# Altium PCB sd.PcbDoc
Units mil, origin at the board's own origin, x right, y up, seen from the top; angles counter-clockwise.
Board outline 6000 x 4000 mil, 2 copper layers (Top Layer, Bottom Layer); 11 components, 11 nets, 49 pads, 4 vias.
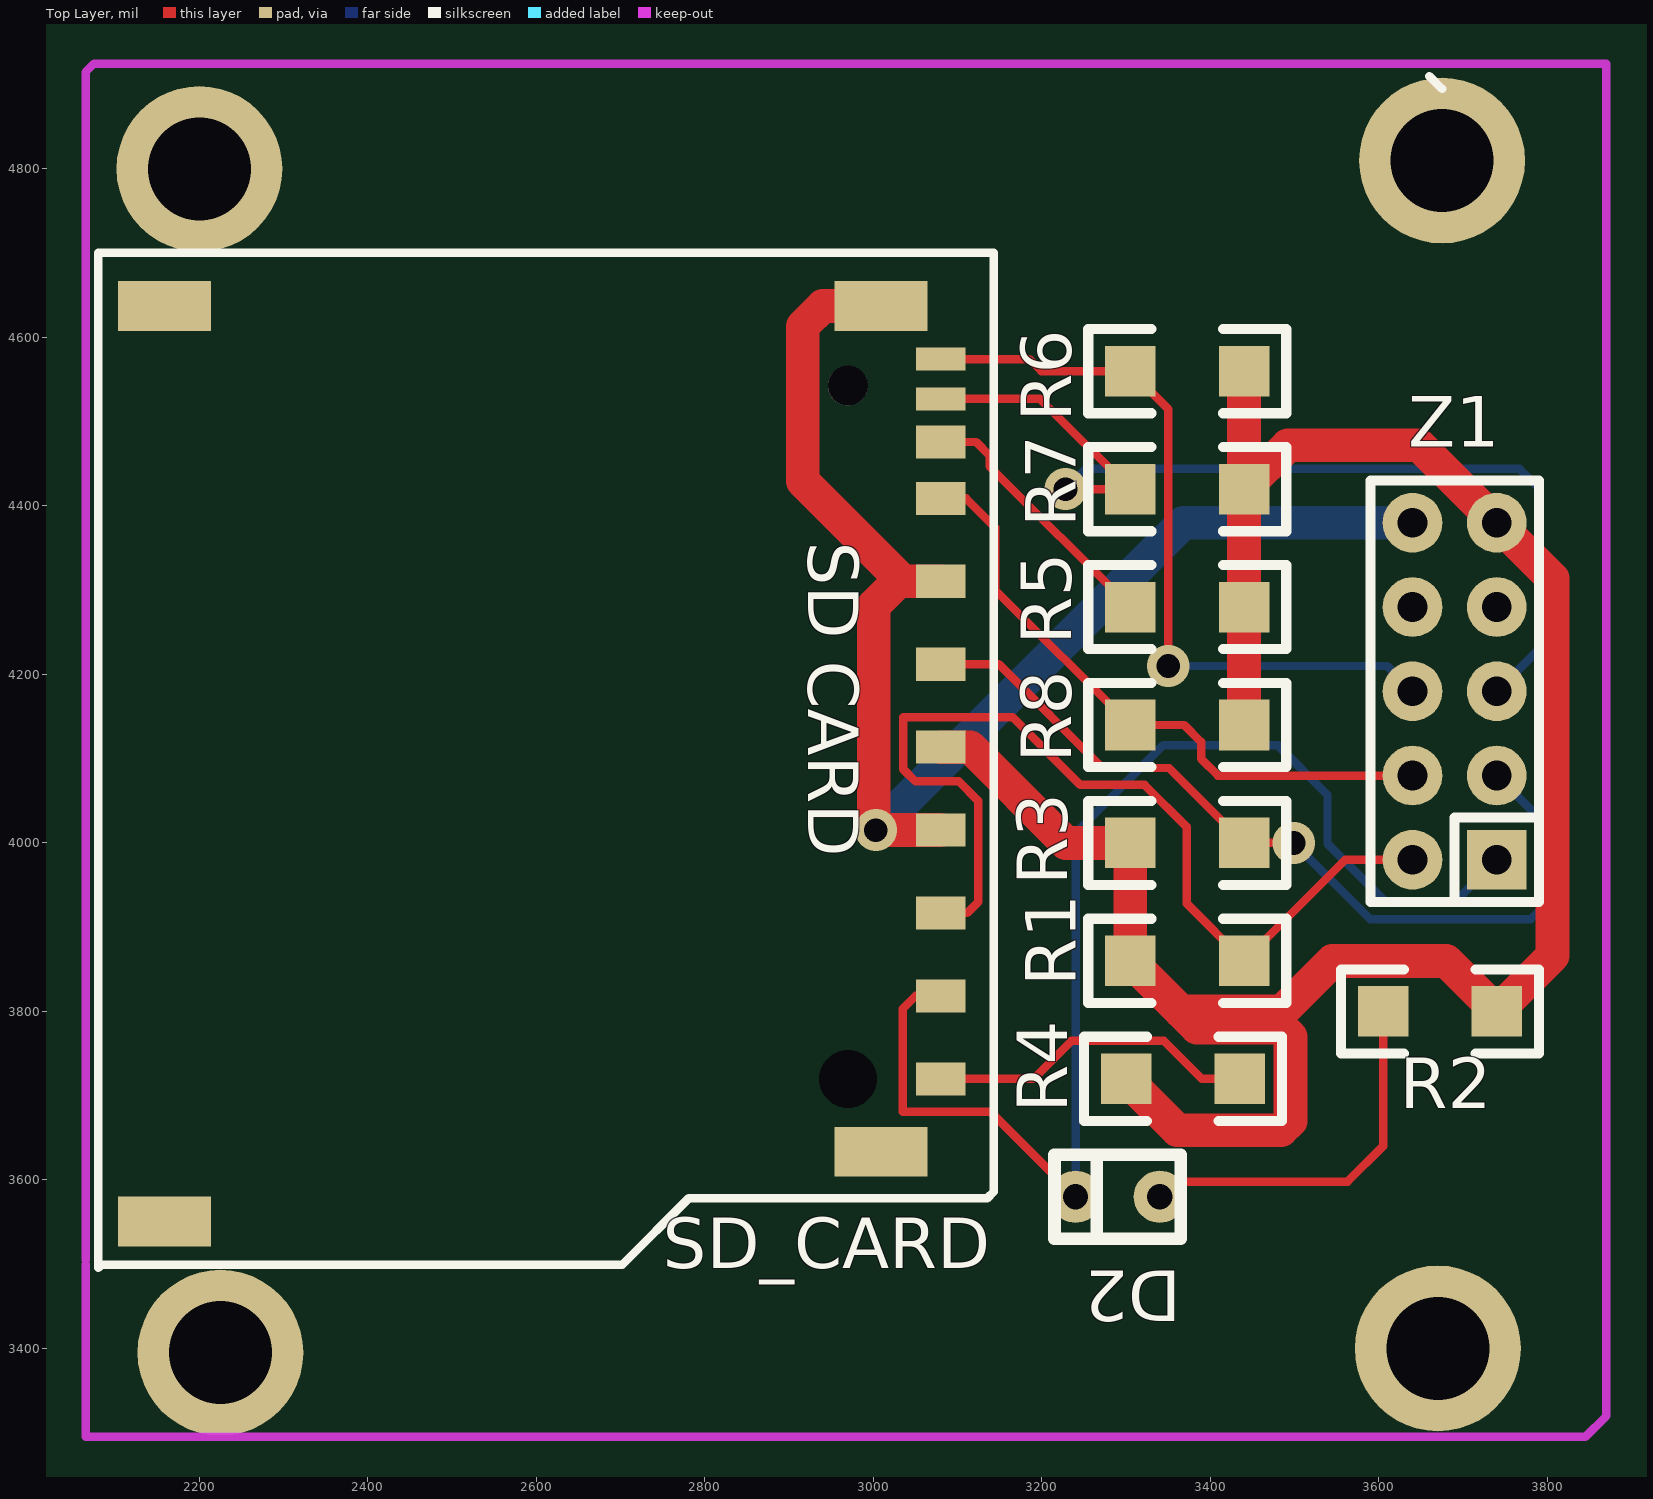
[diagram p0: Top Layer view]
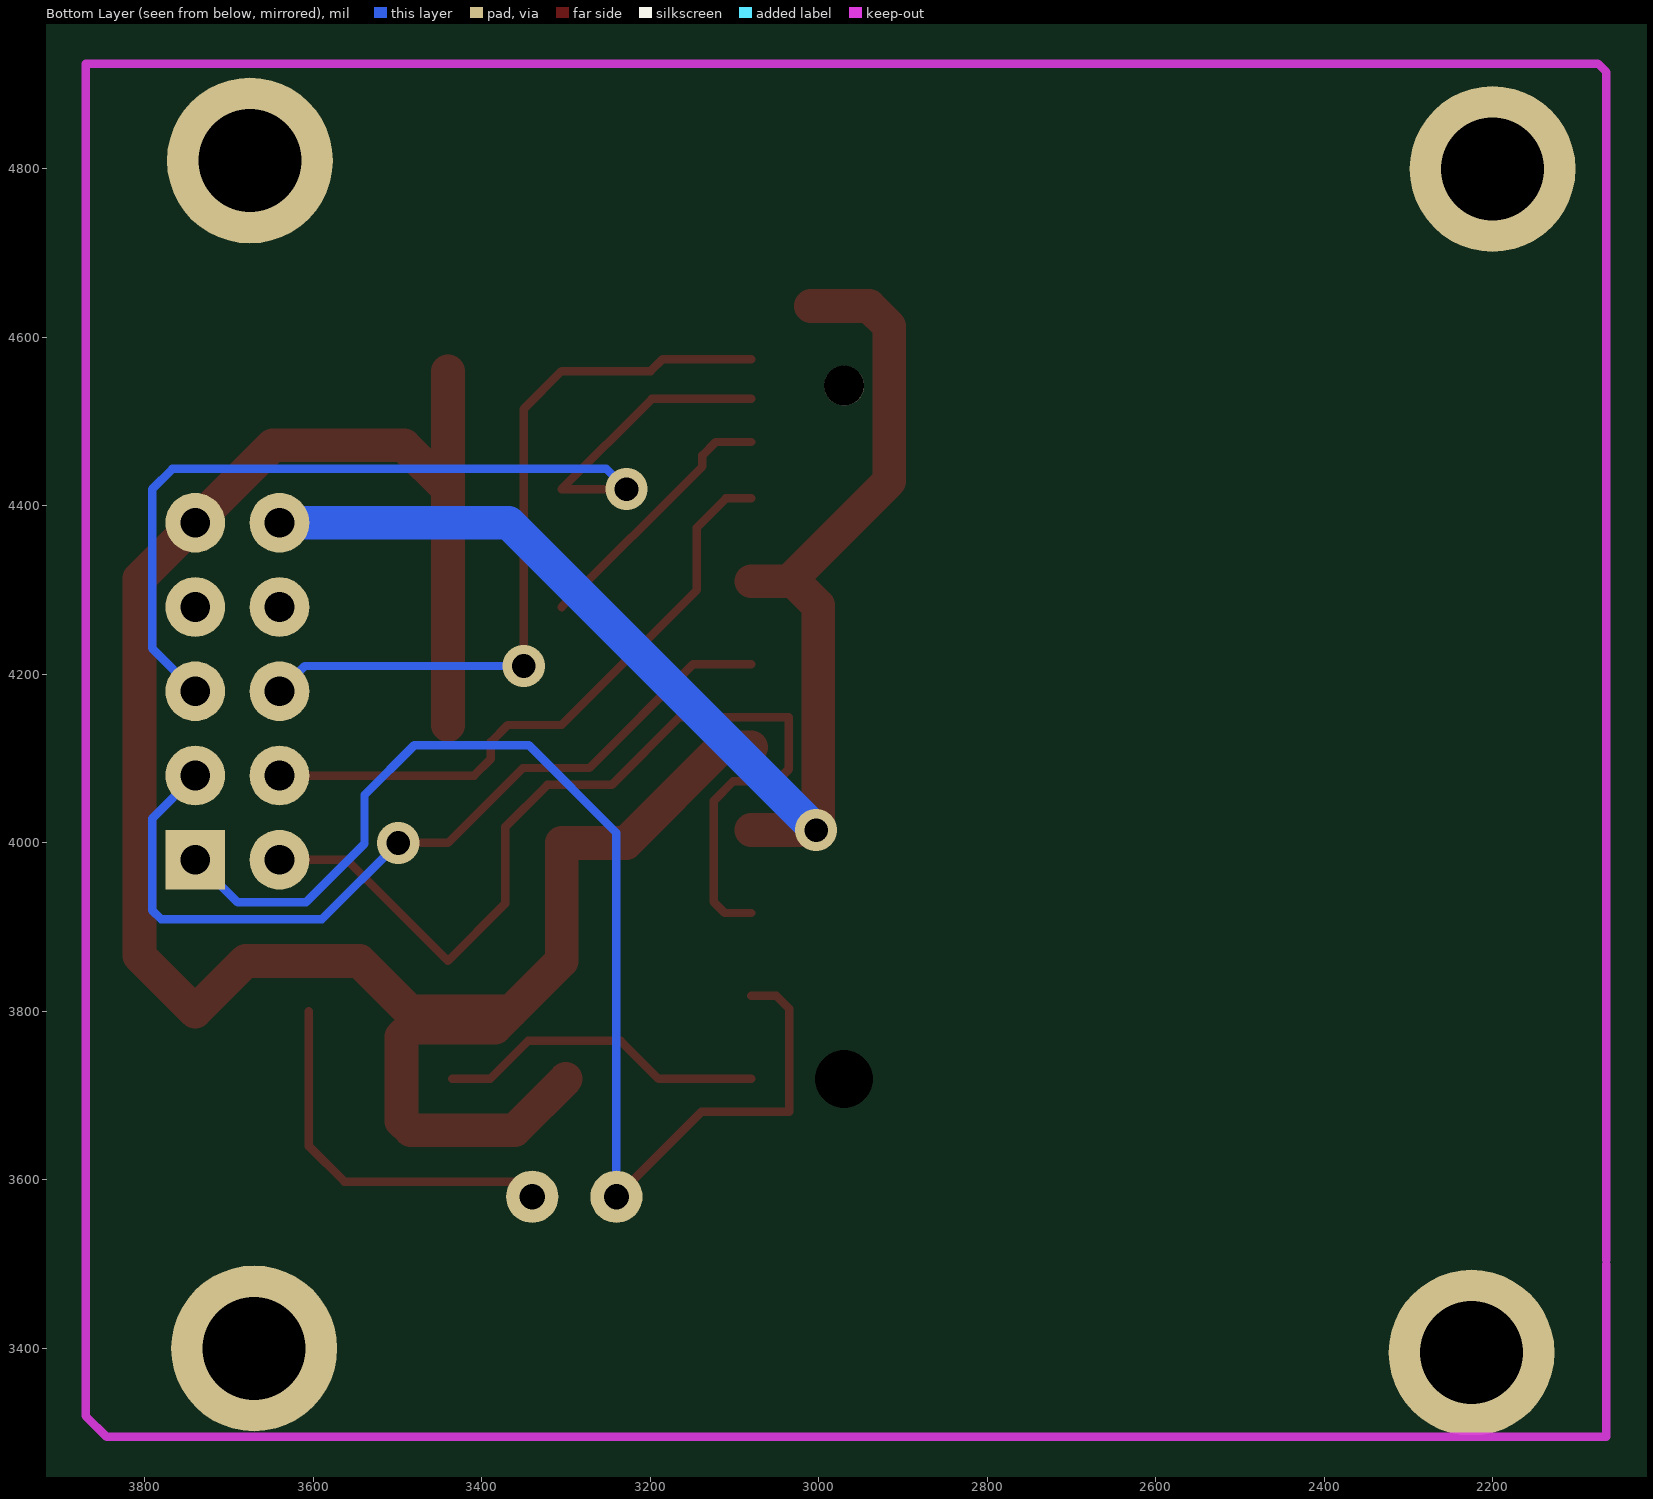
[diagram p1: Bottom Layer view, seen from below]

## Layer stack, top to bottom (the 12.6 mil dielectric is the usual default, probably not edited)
Top Layer: signal copper 1.4
Dielectric: dielectric 12.6, FR-4, Dk 4.8
Bottom Layer: signal copper 1.4

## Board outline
1000,1000 7000,1000 7000,5000 1000,5000

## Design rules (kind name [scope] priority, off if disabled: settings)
Clearance [All] p1: gap=10
PolygonConnect [All] p1: connectstyle=Relief reliefconductorwidth=10 reliefentries=4 polygonreliefangle="90 Angle"
RoutingVias [All] p1: holewidth=28 width=50 viastyle="Through Hole" minholewidth=28 minwidth=50 maxholewidth=28 maxwidth=50
SilkscreenOverComponentPads [All] p1: minsilkscreentomaskgap=10
SolderMaskExpansion [All] p1: expansion=4
Width Width_2 [InNet('GND')] p1: maxlimit=40 minlimit=40 preferedwidth=40
Width Width_1 [InNet('+3,3V')] p2: maxlimit=40 minlimit=40 preferedwidth=40
Width [All] p3: maxlimit=10 minlimit=10 preferedwidth=10
27 further rules are at their usual default settings.

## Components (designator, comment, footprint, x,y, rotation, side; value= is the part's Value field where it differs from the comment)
D2 "" DIODE0.1 3340,3580 r180 top
R1 "10k" 1206 3440,3860 r180 top
R2 "180R" 1206 3740,3800 r180 top
R3 "10k" 1206 3440,4000 r180 top
R4 "10k" 1206 3300,3720 r0 top
R5 "10k" 1206 3440,4280 r180 top
R6 "10k" 1206 3440,4560 r180 top
R7 "10k" 1206 3440,4420 r180 top
R8 "10k" 1206 3440,4140 r180 top
SD_CARD "" CARD_SD 3080,3720 r270 top
Z1 "" IDC10 3740,3980 r90 top

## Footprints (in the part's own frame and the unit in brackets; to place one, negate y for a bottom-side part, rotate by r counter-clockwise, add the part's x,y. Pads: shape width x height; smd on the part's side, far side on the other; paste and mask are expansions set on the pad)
1206 [mil]
  rect 60x60 smd: 1(0,0) 2(135,0)
  silkscreen extent -50,-50 185,50
CARD_SD [mm]
  rect 1.5x2.8 smd: 0(-23.3,-23.4) 0(2.2,-1.8) 0(4.3,-23.4) 12(-23.3,-1.8)
  round 1.2 hole 1.2: 0(-20.9,-2.8)
  round 1.7 hole 1.75: 0(0,-2.8)
  rect 1x1.5 smd: 1(-2.5,0) 2(-5,0) 3(-7.5,0) 4(-10,0) 5(-12.5,0) 6(-15,0) 7(-17.5,0) 8(-19.2,0) 9(0,0)
  rect 0.7x1.5 smd: 10(-20.5,0) 11(-21.7,0)
  silkscreen extent -24.9,-25.4 5.7,1.6
DIODE0.1 [mil]
  round 62 hole 30: A(0,0) K(100,0)
  silkscreen extent -25,-50 125,50
IDC10 [mm]
  rect 1.8x1.8 hole 0.9: 1(0,0)
  round 1.8 hole 0.9: 2(0,2.54) 3(2.54,0) 4(2.54,2.54) 5(5.08,0) 6(5.08,2.54) 7(7.62,0) 8(7.62,2.54) 9(10.16,0) 10(10.16,2.54)
  silkscreen extent -1.27,-1.27 11.43,3.81

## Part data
D2: library part LED
R1 R2 R3 R4 R5 R6 R7 R8: library part RES2
SD_CARD: library part CON12, "Connector"
Z1: library part CON10, "Connector"

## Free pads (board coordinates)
  round 196.85 hole 122.05: 0(3670,3400) 1(3675,4810) 2(2225,3395) 3(2200,4800)

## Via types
v1: diameter 50, hole 28, Top Layer to Bottom Layer, 4 vias

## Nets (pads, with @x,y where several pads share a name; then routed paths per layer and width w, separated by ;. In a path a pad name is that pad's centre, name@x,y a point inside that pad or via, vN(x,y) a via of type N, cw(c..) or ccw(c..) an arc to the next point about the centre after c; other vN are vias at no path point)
+3,3V: R1.2 R2.1 R3.2 R4.1 R5.1 R6.1 R7.1 R8.1 SD_CARD.4 Z1.9 | length 2888.1
  Top Layer w40: SD_CARD.4 3114.97,4113.7 3228.68,4000 R3.2 R1.2 ; R4.1 3361,3659 3484,3659 3495,3670 3495,3770 3484,3781 3384,3781 3365,3800 ; R8.1 R5.1 R7.1 ; R6.1 R7.1 ; R1.2 3365,3800 ; R1.2 3365,3800 ; 3365,3800 3485,3800 3545,3860 3680,3860 R2.1 3806,3866 3806,4314 Z1.9 3648,4472 3492,4472 R7.1
CD_SD: R7.2 SD_CARD.10 Z1.5 | length 1190.4
  Top Layer w10: SD_CARD.10 3197.91,4527.09 R7.2 v1(3228,4420)
  Bottom Layer w10: v1(3228,4420) 3252,4444 3767,4444 3791,4420 3791,4231 Z1.5
CS_SD: D2.K SD_CARD.1 Z1.1 | length 1527.6
  Top Layer w10: SD_CARD.1 3050,3818.43 3035,3803.43 3035,3681 3139,3681 D2.K
  Bottom Layer w10: D2.K 3240,4012 3344,4116 3480,4116 3539,4057 3539,3999 3608.43,3929.57 3689.57,3929.57 Z1.1
DIN_SD: R1.1 SD_CARD.2 Z1.2 | length 1163.3
  Top Layer w10: SD_CARD.2 3111.38,3916.85 3124.53,3930 3124.53,4050 3101.53,4073 3050,4073 3035.47,4087.53 3035.47,4149 3165.5,4149 3245.5,4069 3322,4069 3372,4019 3372,3928 R1.1 3560,3980 Z1.2
GND: SD_CARD.3 SD_CARD.6 SD_CARD.12 Z1.10 | length 1724.2
  Top Layer w40: SD_CARD.12 2940,4637.32 2916,4613.32 2916,4429.55 3035,4310.55 ; SD_CARD.3 v1(3003,4015.28) 3000.47,4017.8 3000.47,4281.81 3029.21,4310.55 3035,4310.55 ; 3035,4310.55 SD_CARD.6 3035,4310.55
  Bottom Layer w40: v1(3003,4015.28) 3367.72,4380 Z1.10
NetD2_A: D2.A R2.2 | length 449.9
  Top Layer w10: D2.A 3358,3598 3563,3598 3605,3640 R2.2
NetR4_2: R4.2 SD_CARD.9 | length 392.3
  Top Layer w10: SD_CARD.9 3190,3720 3235,3765 3345,3765 3390,3720 R4.2
NetR5_2: R5.2 SD_CARD.8 | length 313.8
  Top Layer w10: SD_CARD.8 3122.09,4475.91 3138,4460 3138,4447 R5.2
SCK_IN_SD: R3.1 SD_CARD.5 Z1.3 | length 1021.8
  Top Layer w10: SD_CARD.5 3149.01,4212.13 3272.13,4089 3351,4089 R3.1 v1(3499,4000)
  Bottom Layer w10: v1(3499,4000) 3589.43,3909.57 3780.57,3909.57 3791,3920 3791,4029 Z1.3
SDO_SD: R8.2 SD_CARD.7 Z1.4 | length 751.3
  Top Layer w10: SD_CARD.7 3110,4408.98 3144.53,4374.45 3144.53,4300.47 R8.2 3369,4140 3389,4120 3389,4100 3409,4080 Z1.4
WD_SD: R6.2 SD_CARD.11 Z1.6 | length 902
  Top Layer w10: SD_CARD.11 3185,4574.33 3199.33,4560 R6.2 3350,4515 v1(3350,4210)
  Bottom Layer w10: v1(3350,4210) 3610,4210 Z1.6
pads on no net: SD_CARD.0 Z1.7 Z1.8

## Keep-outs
Keep-Out Layer:
  lines w10: 2065,3500 2065,3295 3845,3295 3870,3320 3870,4925 2075,4925 2065,4915 2065,3505

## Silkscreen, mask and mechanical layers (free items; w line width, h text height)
Top Overlay:
  lines w10: 3660,4910 3675,4895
